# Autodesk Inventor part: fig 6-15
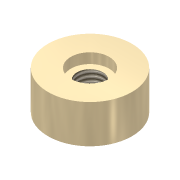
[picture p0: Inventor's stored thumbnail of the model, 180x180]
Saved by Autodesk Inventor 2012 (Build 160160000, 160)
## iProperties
Shininess: 65.0
Angle Display Precision: 2
Document Length Units: 11269
Document Angle Units: 11279
Document Time Units: 11290
Document Mass Units: 11283
Document Length Units Precision: 3
Document Angle Units Precision: 2
Created: 2001-11
Part Number: fig 6-15
Document SubType Name: Modeling
Designer: Renu Muthoo
Density: 1 g/cm^3
Material: Default
Density: 0.0
Volumn: 0.0
Area: 0.0
PropertySet Name: Model Information
Control State: 0
Master: False
Checked Out: False
Author: Renu Muthoo
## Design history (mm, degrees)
sketch "Sketch1"
  geometry: C1 r 16.401 at (0, 0)
  constraints: 1 centre point
extrude "Extrusion1" new body sketch "Sketch1" distance "d0" = 15; taper "d1" = 0 deg
hole "Hole3" diameter "d18" = 10.106; stored, may be unused: countersink angle "d22" = 90 deg, drill point angle "d24" = 118 deg; dims "d16" = 10, "d17" = 10, "d19" = 6, "d20" = 15, "d21" = 4, "d23" = 10
body "Solid1"
